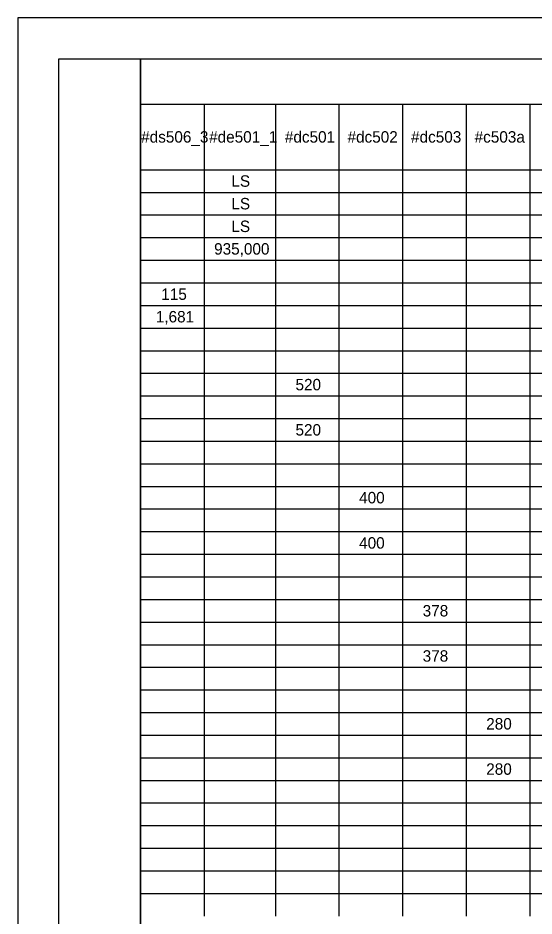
# Model space of a CAD drawing. Extents: x 0.2 to 34.2, y 0 to 22.
# Drawn here: x 0.19 to 6.5, y 11.04 to 22.03 of the extents above; entities that cross this region are included whole.
import ezdxf

# ---------------------------------------------------------------- set-up
doc = ezdxf.new("R2010")
doc.units = 0
for name, color, linetype in [('Default', 7, 'Continuous'), ('SH_Border', 7, 'Continuous'), ('SH_Cut_Line', 7, 'Continuous')]:
    doc.layers.add(name, color=color, linetype=linetype)

msp = doc.modelspace()

# ---------------------------------------------------------------- linework, layer by layer
at = {"layer": 'Default'}
for p, q in [((1.692, 21.525), (4.894, 21.525)), ((4.894, 21.525), (8.004, 21.525)), ((1.692, 20.972), (4.894, 20.972)), ((1.692, 20.972), (1.692, 20.722)), ((2.469, 20.972), (2.469, 20.722)), ((3.339, 20.972), (3.339, 20.722)), ((4.116, 20.972), (4.116, 20.722)), ((4.894, 20.972), (8.004, 20.972)), ((4.894, 20.972), (4.894, 20.722)), ((5.671, 20.972), (5.671, 20.722)), ((6.449, 20.972), (6.449, 20.722)), ((1.692, 20.722), (1.692, 20.445)), ((2.469, 20.722), (2.469, 20.445)), ((3.339, 20.722), (3.339, 20.445)), ((4.116, 20.722), (4.116, 20.445)), ((4.894, 20.722), (4.894, 20.445)), ((5.671, 20.722), (5.671, 20.445)), ((6.449, 20.722), (6.449, 20.445)), ((1.692, 20.445), (1.692, 20.168)), ((2.469, 20.445), (2.469, 20.168)), ((3.339, 20.445), (3.339, 20.168)), ((4.116, 20.445), (4.116, 20.168)), ((4.894, 20.445), (4.894, 20.168)), ((5.671, 20.445), (5.671, 20.168)), ((6.449, 20.445), (6.449, 20.168)), ((1.692, 20.168), (4.894, 20.168)), ((1.692, 20.168), (1.692, 19.891)), ((2.469, 20.168), (2.469, 19.891)), ((3.339, 20.168), (3.339, 19.891)), ((4.116, 20.168), (4.116, 19.891)), ((4.894, 20.168), (8.004, 20.168)), ((4.894, 20.168), (4.894, 19.891)), ((5.671, 20.168), (5.671, 19.891)), ((6.449, 20.168), (6.449, 19.891)), ((1.692, 19.891), (4.894, 19.891)), ((1.692, 19.891), (1.692, 19.615)), ((2.469, 19.891), (2.469, 19.615)), ((3.339, 19.891), (3.339, 19.615)), ((4.116, 19.891), (4.116, 19.615)), ((4.894, 19.891), (8.004, 19.891)), ((4.894, 19.891), (4.894, 19.615)), ((5.671, 19.891), (5.671, 19.615)), ((6.449, 19.891), (6.449, 19.615)), ((1.692, 19.615), (4.894, 19.615)), ((1.692, 19.615), (1.692, 19.338)), ((2.469, 19.615), (2.469, 19.338)), ((3.339, 19.615), (3.339, 19.338)), ((4.116, 19.615), (4.116, 19.338)), ((4.894, 19.615), (8.004, 19.615)), ((4.894, 19.615), (4.894, 19.338)), ((5.671, 19.615), (5.671, 19.338)), ((6.449, 19.615), (6.449, 19.338)), ((1.692, 19.338), (4.894, 19.338)), ((1.692, 19.338), (1.692, 19.061)), ((2.469, 19.338), (2.469, 19.061)), ((3.339, 19.338), (3.339, 19.061)), ((4.116, 19.338), (4.116, 19.061)), ((4.894, 19.338), (8.004, 19.338)), ((4.894, 19.338), (4.894, 19.061)), ((5.671, 19.338), (5.671, 19.061)), ((6.449, 19.338), (6.449, 19.061)), ((1.692, 19.061), (4.894, 19.061)), ((1.692, 19.061), (1.692, 18.785)), ((2.469, 19.061), (2.469, 18.785)), ((3.339, 19.061), (3.339, 18.785)), ((4.116, 19.061), (4.116, 18.785)), ((4.894, 19.061), (8.004, 19.061)), ((4.894, 19.061), (4.894, 18.785)), ((5.671, 19.061), (5.671, 18.785)), ((6.449, 19.061), (6.449, 18.785)), ((1.692, 18.785), (4.894, 18.785)), ((1.692, 18.785), (1.692, 18.508)), ((2.469, 18.785), (2.469, 18.508)), ((3.339, 18.785), (3.339, 18.508)), ((4.116, 18.785), (4.116, 18.508)), ((4.894, 18.785), (8.004, 18.785)), ((4.894, 18.785), (4.894, 18.508)), ((5.671, 18.785), (5.671, 18.508)), ((6.449, 18.785), (6.449, 18.508)), ((1.692, 18.508), (4.894, 18.508)), ((1.692, 18.508), (1.692, 18.231)), ((2.469, 18.508), (2.469, 18.231)), ((3.339, 18.508), (3.339, 18.231)), ((4.116, 18.508), (4.116, 18.231)), ((4.894, 18.508), (8.004, 18.508)), ((4.894, 18.508), (4.894, 18.231)), ((5.671, 18.508), (5.671, 18.231)), ((6.449, 18.508), (6.449, 18.231)), ((1.692, 18.231), (4.894, 18.231)), ((1.692, 18.231), (1.692, 17.954)), ((2.469, 18.231), (2.469, 17.954)), ((3.339, 18.231), (3.339, 17.954)), ((4.116, 18.231), (4.116, 17.954)), ((4.894, 18.231), (8.004, 18.231)), ((4.894, 18.231), (4.894, 17.954)), ((5.671, 18.231), (5.671, 17.954)), ((6.449, 18.231), (6.449, 17.954)), ((1.692, 17.954), (4.894, 17.954)), ((1.692, 17.954), (1.692, 17.678)), ((2.469, 17.954), (2.469, 17.678)), ((3.339, 17.954), (3.339, 17.678)), ((4.116, 17.954), (4.116, 17.678)), ((4.894, 17.954), (8.004, 17.954)), ((4.894, 17.954), (4.894, 17.678)), ((5.671, 17.954), (5.671, 17.678)), ((6.449, 17.954), (6.449, 17.678)), ((1.692, 17.678), (4.894, 17.678)), ((1.692, 17.678), (1.692, 17.401)), ((2.469, 17.678), (2.469, 17.401)), ((3.339, 17.678), (3.339, 17.401)), ((4.116, 17.678), (4.116, 17.401)), ((4.894, 17.678), (8.004, 17.678)), ((4.894, 17.678), (4.894, 17.401)), ((5.671, 17.678), (5.671, 17.401)), ((6.449, 17.678), (6.449, 17.401)), ((1.692, 17.401), (4.894, 17.401)), ((1.692, 17.401), (1.692, 17.124)), ((2.469, 17.401), (2.469, 17.124)), ((3.339, 17.401), (3.339, 17.124)), ((4.116, 17.401), (4.116, 17.124)), ((4.894, 17.401), (8.004, 17.401)), ((4.894, 17.401), (4.894, 17.124)), ((5.671, 17.401), (5.671, 17.124)), ((6.449, 17.401), (6.449, 17.124)), ((1.692, 17.124), (4.894, 17.124)), ((1.692, 17.124), (1.692, 16.848)), ((2.469, 17.124), (2.469, 16.848)), ((3.339, 17.124), (3.339, 16.848)), ((4.116, 17.124), (4.116, 16.848)), ((4.894, 17.124), (8.004, 17.124)), ((4.894, 17.124), (4.894, 16.848)), ((5.671, 17.124), (5.671, 16.848)), ((6.449, 17.124), (6.449, 16.848)), ((1.692, 16.848), (4.894, 16.848)), ((1.692, 16.848), (1.692, 16.571)), ((2.469, 16.848), (2.469, 16.571)), ((3.339, 16.848), (3.339, 16.571)), ((4.116, 16.848), (4.116, 16.571)), ((4.894, 16.848), (8.004, 16.848)), ((4.894, 16.848), (4.894, 16.571)), ((5.671, 16.848), (5.671, 16.571)), ((6.449, 16.848), (6.449, 16.571)), ((1.692, 16.571), (4.894, 16.571)), ((1.692, 16.571), (1.692, 16.294)), ((2.469, 16.571), (2.469, 16.294)), ((3.339, 16.571), (3.339, 16.294)), ((4.116, 16.571), (4.116, 16.294)), ((4.894, 16.571), (8.004, 16.571)), ((4.894, 16.571), (4.894, 16.294)), ((5.671, 16.571), (5.671, 16.294)), ((6.449, 16.571), (6.449, 16.294)), ((1.692, 16.294), (4.894, 16.294)), ((1.692, 16.294), (1.692, 16.018)), ((2.469, 16.294), (2.469, 16.018)), ((3.339, 16.294), (3.339, 16.018)), ((4.116, 16.294), (4.116, 16.018)), ((4.894, 16.294), (8.004, 16.294)), ((4.894, 16.294), (4.894, 16.018)), ((5.671, 16.294), (5.671, 16.018)), ((6.449, 16.294), (6.449, 16.018)), ((1.692, 16.018), (4.894, 16.018)), ((1.692, 16.018), (1.692, 15.741)), ((2.469, 16.018), (2.469, 15.741)), ((3.339, 16.018), (3.339, 15.741)), ((4.116, 16.018), (4.116, 15.741)), ((4.894, 16.018), (8.004, 16.018)), ((4.894, 16.018), (4.894, 15.741)), ((5.671, 16.018), (5.671, 15.741)), ((6.449, 16.018), (6.449, 15.741)), ((1.692, 15.741), (4.894, 15.741)), ((1.692, 15.741), (1.692, 15.464)), ((2.469, 15.741), (2.469, 15.464)), ((3.339, 15.741), (3.339, 15.464)), ((4.116, 15.741), (4.116, 15.464)), ((4.894, 15.741), (8.004, 15.741)), ((4.894, 15.741), (4.894, 15.464)), ((5.671, 15.741), (5.671, 15.464)), ((6.449, 15.741), (6.449, 15.464)), ((1.692, 15.464), (4.894, 15.464)), ((1.692, 15.464), (1.692, 15.187)), ((2.469, 15.464), (2.469, 15.187)), ((3.339, 15.464), (3.339, 15.187)), ((4.116, 15.464), (4.116, 15.187)), ((4.894, 15.464), (8.004, 15.464)), ((4.894, 15.464), (4.894, 15.187)), ((5.671, 15.464), (5.671, 15.187)), ((6.449, 15.464), (6.449, 15.187)), ((1.692, 15.187), (4.894, 15.187)), ((1.692, 15.187), (1.692, 14.911)), ((2.469, 15.187), (2.469, 14.911)), ((3.339, 15.187), (3.339, 14.911)), ((4.116, 15.187), (4.116, 14.911)), ((4.894, 15.187), (8.004, 15.187)), ((4.894, 15.187), (4.894, 14.911)), ((5.671, 15.187), (5.671, 14.911)), ((6.449, 15.187), (6.449, 14.911)), ((1.692, 14.911), (4.894, 14.911)), ((1.692, 14.911), (1.692, 14.634)), ((2.469, 14.911), (2.469, 14.634)), ((3.339, 14.911), (3.339, 14.634)), ((4.116, 14.911), (4.116, 14.634)), ((4.894, 14.911), (8.004, 14.911)), ((4.894, 14.911), (4.894, 14.634)), ((5.671, 14.911), (5.671, 14.634)), ((6.449, 14.911), (6.449, 14.634)), ((1.692, 14.634), (4.894, 14.634)), ((1.692, 14.634), (1.692, 14.357)), ((2.469, 14.634), (2.469, 14.357)), ((3.339, 14.634), (3.339, 14.357)), ((4.116, 14.634), (4.116, 14.357)), ((4.894, 14.634), (8.004, 14.634)), ((4.894, 14.634), (4.894, 14.357)), ((5.671, 14.634), (5.671, 14.357)), ((6.449, 14.634), (6.449, 14.357)), ((1.692, 14.357), (4.894, 14.357)), ((1.692, 14.357), (1.692, 14.081)), ((2.469, 14.357), (2.469, 14.081)), ((3.339, 14.357), (3.339, 14.081)), ((4.116, 14.357), (4.116, 14.081)), ((4.894, 14.357), (8.004, 14.357)), ((4.894, 14.357), (4.894, 14.081)), ((5.671, 14.357), (5.671, 14.081)), ((6.449, 14.357), (6.449, 14.081)), ((1.692, 14.081), (4.894, 14.081)), ((1.692, 14.081), (1.692, 13.804)), ((2.469, 14.081), (2.469, 13.804)), ((3.339, 14.081), (3.339, 13.804)), ((4.116, 14.081), (4.116, 13.804)), ((4.894, 14.081), (8.004, 14.081)), ((4.894, 14.081), (4.894, 13.804)), ((5.671, 14.081), (5.671, 13.804)), ((6.449, 14.081), (6.449, 13.804)), ((1.692, 13.804), (4.894, 13.804)), ((1.692, 13.804), (1.692, 13.527)), ((2.469, 13.804), (2.469, 13.527)), ((3.339, 13.804), (3.339, 13.527)), ((4.116, 13.804), (4.116, 13.527)), ((4.894, 13.804), (8.004, 13.804)), ((4.894, 13.804), (4.894, 13.527)), ((5.671, 13.804), (5.671, 13.527)), ((6.449, 13.804), (6.449, 13.527)), ((1.692, 13.527), (4.894, 13.527)), ((1.692, 13.527), (1.692, 13.25)), ((2.469, 13.527), (2.469, 13.25)), ((3.339, 13.527), (3.339, 13.25)), ((4.116, 13.527), (4.116, 13.25)), ((4.894, 13.527), (8.004, 13.527)), ((4.894, 13.527), (4.894, 13.25)), ((5.671, 13.527), (5.671, 13.25)), ((6.449, 13.527), (6.449, 13.25)), ((1.692, 13.25), (4.894, 13.25)), ((1.692, 13.25), (1.692, 12.974)), ((2.469, 13.25), (2.469, 12.974)), ((3.339, 13.25), (3.339, 12.974)), ((4.116, 13.25), (4.116, 12.974)), ((4.894, 13.25), (8.004, 13.25)), ((4.894, 13.25), (4.894, 12.974)), ((5.671, 13.25), (5.671, 12.974)), ((6.449, 13.25), (6.449, 12.974)), ((1.692, 12.974), (4.894, 12.974)), ((1.692, 12.974), (1.692, 12.697)), ((2.469, 12.974), (2.469, 12.697)), ((3.339, 12.974), (3.339, 12.697)), ((4.116, 12.974), (4.116, 12.697)), ((4.894, 12.974), (8.004, 12.974)), ((4.894, 12.974), (4.894, 12.697)), ((5.671, 12.974), (5.671, 12.697)), ((6.449, 12.974), (6.449, 12.697)), ((1.692, 12.697), (4.894, 12.697)), ((1.692, 12.697), (1.692, 12.42)), ((2.469, 12.697), (2.469, 12.42)), ((3.339, 12.697), (3.339, 12.42)), ((4.116, 12.697), (4.116, 12.42)), ((4.894, 12.697), (8.004, 12.697)), ((4.894, 12.697), (4.894, 12.42)), ((5.671, 12.697), (5.671, 12.42)), ((6.449, 12.697), (6.449, 12.42)), ((1.692, 12.42), (4.894, 12.42)), ((1.692, 12.42), (1.692, 12.144)), ((2.469, 12.42), (2.469, 12.144)), ((3.339, 12.42), (3.339, 12.144)), ((4.116, 12.42), (4.116, 12.144)), ((4.894, 12.42), (8.004, 12.42)), ((4.894, 12.42), (4.894, 12.144)), ((5.671, 12.42), (5.671, 12.144)), ((6.449, 12.42), (6.449, 12.144)), ((1.692, 12.144), (4.894, 12.144)), ((1.692, 12.144), (1.692, 11.867)), ((2.469, 12.144), (2.469, 11.867)), ((3.339, 12.144), (3.339, 11.867)), ((4.116, 12.144), (4.116, 11.867)), ((4.894, 12.144), (8.004, 12.144)), ((4.894, 12.144), (4.894, 11.867)), ((5.671, 12.144), (5.671, 11.867)), ((6.449, 12.144), (6.449, 11.867)), ((1.692, 11.867), (4.894, 11.867)), ((1.692, 11.867), (1.692, 11.59)), ((2.469, 11.867), (2.469, 11.59)), ((3.339, 11.867), (3.339, 11.59)), ((4.116, 11.867), (4.116, 11.59)), ((4.894, 11.867), (8.004, 11.867)), ((4.894, 11.867), (4.894, 11.59)), ((5.671, 11.867), (5.671, 11.59)), ((6.449, 11.867), (6.449, 11.59)), ((1.692, 11.59), (4.894, 11.59)), ((1.692, 11.59), (1.692, 11.314)), ((2.469, 11.59), (2.469, 11.314)), ((3.339, 11.59), (3.339, 11.314)), ((4.116, 11.59), (4.116, 11.314)), ((4.894, 11.59), (8.004, 11.59)), ((4.894, 11.59), (4.894, 11.314)), ((5.671, 11.59), (5.671, 11.314)), ((6.449, 11.59), (6.449, 11.314)), ((1.692, 11.314), (4.894, 11.314)), ((1.692, 11.314), (1.692, 11.037)), ((2.469, 11.314), (2.469, 11.037)), ((3.339, 11.314), (3.339, 11.037)), ((4.116, 11.314), (4.116, 11.037)), ((4.894, 11.314), (8.004, 11.314)), ((4.894, 11.314), (4.894, 11.037)), ((5.671, 11.314), (5.671, 11.037)), ((6.449, 11.314), (6.449, 11.037))]:
    msp.add_line(p, q, dxfattribs=at)
at = {"layer": 'SH_Border'}
for points in [[(0.692, 21.525), (1.692, 21.525), (1.692, 0.525), (0.692, 0.525)], [(1.692, 21.525), (33.692, 21.525), (33.692, 0.525), (1.692, 0.525)]]:
    msp.add_lwpolyline(points, close=True, dxfattribs=at)
at = {"layer": 'SH_Cut_Line'}
msp.add_lwpolyline([(0.192, 0.025), (34.192, 0.025), (34.192, 22.025), (0.192, 22.025)], close=True, dxfattribs=at)

# ---------------------------------------------------------------- texts
at = {"layer": 'Default'}
for s, p in [('#ds506_3', (1.698, 20.5)), ('#de501_1', (2.529, 20.5)), ('#dc501', (3.455, 20.5)), ('#dc502', (4.221, 20.5)), ('#dc503', (4.998, 20.5)), ('#c503a', (5.775, 20.5)), ('LS', (2.801, 19.96)), ('LS', (2.801, 19.683)), ('LS', (2.801, 19.406)), ('935,000', (2.59, 19.13)), ('115', (1.944, 18.576)), ('1,681', (1.877, 18.3)), ('520', (3.585, 17.469)), ('520', (3.585, 16.916)), ('400', (4.363, 16.086)), ('400', (4.363, 15.532)), ('378', (5.14, 14.702)), ('378', (5.14, 14.149)), ('280', (5.917, 13.319)), ('280', (5.917, 12.765))]:
    msp.add_text(s, height=0.14, dxfattribs=at).set_placement(p)

doc.saveas('drawing.dxf')
